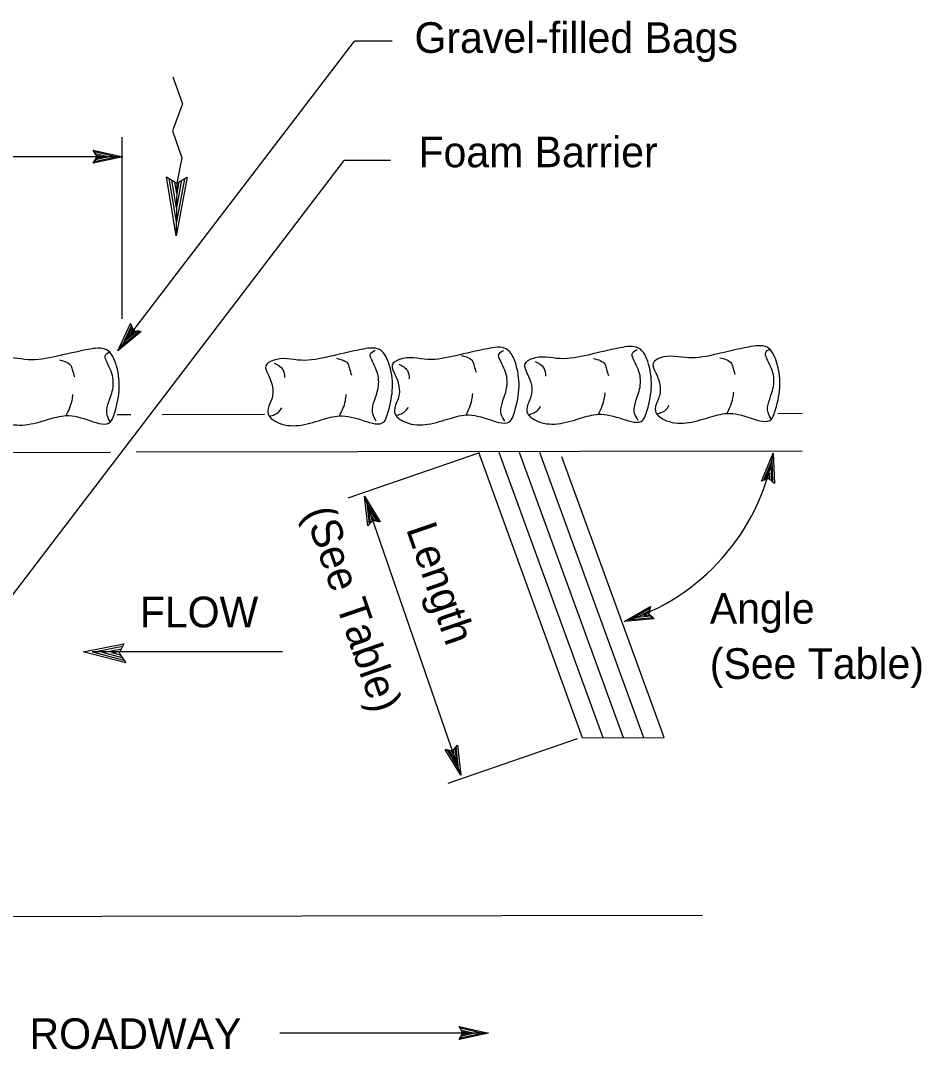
# Model space of a CAD drawing. Extents: x 6708945 to 6710368, y 1871409 to 1872338.
# Drawn here: x 6709914.8 to 6710091.1, y 1871506.8 to 1871708.2 of the extents above; entities that cross this region are included whole.
import ezdxf

# ---------------------------------------------------------------- set-up
doc = ezdxf.new("R2010")
doc.units = 0
for name, color, linetype in [('57 Undefined', 7, 'Continuous'), ('60 Nongeo Data', 7, 'Continuous'), ('63 Undefined', 7, 'Continuous')]:
    doc.layers.add(name, color=color, linetype=linetype)

msp = doc.modelspace()

# ---------------------------------------------------------------- linework, layer by layer
at = {"layer": '57 Undefined'}
for p, q in [((6709933.85, 1871643.55), (6709980.14, 1871704.21)), ((6709987.5, 1871704.21), (6709980.14, 1871704.21)), ((6709934.7, 1871649.82), (6709934.7, 1871685.42)), ((6709934.78, 1871681.58), (6709884.17, 1871681.58)), ((6709905.48, 1871585.64), (6709978.12, 1871680.81)), ((6709987.19, 1871680.81), (6709978.12, 1871680.81)), ((6710004.42, 1871623.57), (6709978.85, 1871614.76)), ((6710000.95, 1871560.49), (6709982.12, 1871615.15)), ((6710023.7, 1871567.6), (6709998.43, 1871558.89)), ((6710006.36, 1871510.02), (6709965.53, 1871510.02))]:
    msp.add_line(p, q, dxfattribs=at)
msp.add_arc((6710020.27, 1871631.22), 42.56, 287.3352, 349.5749, dxfattribs=at)
at = {"layer": '60 Nongeo Data'}
for p, q in [((6709929.02, 1871682.87), (6709929.02, 1871682.87)), ((6709934.78, 1871681.58), (6709934.78, 1871681.58)), ((6709929.02, 1871680.3), (6709929.02, 1871680.3)), ((6709936.33, 1871648.91), (6709936.33, 1871648.91)), ((6709938.36, 1871647.35), (6709938.36, 1871647.35)), ((6709933.85, 1871643.55), (6709933.85, 1871643.55)), ((6710024.8, 1871567.85), (6710004.48, 1871623.68)), ((6710028.79, 1871567.83), (6710008.46, 1871623.69)), ((6710032.77, 1871567.83), (6710012.44, 1871623.69)), ((6710036.76, 1871567.83), (6710016.42, 1871623.7)), ((6710040.73, 1871567.87), (6710020.73, 1871622.81)), ((6710062.12, 1871623.52), (6710062.12, 1871623.52)), ((6710059.82, 1871618.09), (6710059.82, 1871618.09)), ((6710062.34, 1871617.63), (6710062.34, 1871617.63)), ((6709982.12, 1871615.15), (6709982.12, 1871615.15)), ((6709982.78, 1871609.29), (6709982.78, 1871609.29)), ((6709985.2, 1871610.12), (6709985.2, 1871610.12)), ((6710038.07, 1871593.53), (6710038.07, 1871593.53)), ((6710032.95, 1871590.6), (6710032.95, 1871590.6)), ((6710038.83, 1871591.09), (6710038.83, 1871591.09)), ((6709927.04, 1871584.63), (6709934.97, 1871586.24)), ((6709935.39, 1871582.48), (6709927.04, 1871584.63)), ((6709927.04, 1871584.63), (6709927.04, 1871584.63)), ((6709966.02, 1871584.63), (6709928.77, 1871584.63)), ((6709935.04, 1871582.99), (6709928.91, 1871584.57)), ((6709928.92, 1871584.58), (6709934.71, 1871585.75)), ((6709930.79, 1871584.51), (6709934.52, 1871585.27)), ((6709934.66, 1871583.51), (6709930.79, 1871584.51)), ((6709932.66, 1871584.44), (6709934.26, 1871584.77)), ((6709934.37, 1871584), (6709932.66, 1871584.44)), ((6709934.97, 1871586.24), (6709934.09, 1871584.4)), ((6709934.09, 1871584.4), (6709935.39, 1871582.48)), ((6709934.97, 1871586.24), (6709934.97, 1871586.24)), ((6709935.39, 1871582.48), (6709935.39, 1871582.48)), ((6710000.29, 1871566.36), (6710000.29, 1871566.36)), ((6709997.87, 1871565.52), (6709997.87, 1871565.52)), ((6710000.95, 1871560.49), (6710000.95, 1871560.49)), ((6710000.6, 1871511.3), (6710000.6, 1871511.3)), ((6710006.36, 1871510.02), (6710006.36, 1871510.02)), ((6710000.6, 1871508.74), (6710000.6, 1871508.74))]:
    msp.add_line(p, q, dxfattribs=at)
for points in [[(6709929.02, 1871682.87), (6709934.78, 1871681.58), (6709929.02, 1871680.3), (6709929.22, 1871680.64), (6709933.44, 1871681.58), (6709929.22, 1871682.53), (6709929.43, 1871682.19), (6709932.13, 1871681.58), (6709929.43, 1871680.99), (6709929.63, 1871681.33), (6709930.8, 1871681.58), (6709929.63, 1871681.85), (6709929.79, 1871681.58), (6709929.02, 1871680.3), (6709929.79, 1871681.58)], [(6709938.36, 1871647.35), (6709933.85, 1871643.55), (6709936.33, 1871648.91), (6709936.47, 1871648.54), (6709934.65, 1871644.62), (6709937.97, 1871647.4), (6709937.58, 1871647.44), (6709935.46, 1871645.66), (6709936.62, 1871648.17), (6709936.77, 1871647.8), (6709936.26, 1871646.71), (6709937.18, 1871647.49), (6709936.88, 1871647.52), (6709936.33, 1871648.91), (6709936.88, 1871647.52)], [(6710059.82, 1871618.09), (6710062.12, 1871623.52), (6710062.34, 1871617.63), (6710062.04, 1871617.89), (6710061.89, 1871622.21), (6710060.19, 1871618.23), (6710060.56, 1871618.37), (6710061.64, 1871620.91), (6710061.74, 1871618.15), (6710061.45, 1871618.42), (6710061.4, 1871619.61), (6710060.93, 1871618.51), (6710061.22, 1871618.61), (6710062.34, 1871617.63), (6710061.22, 1871618.61)], [(6709982.78, 1871609.29), (6709982.12, 1871615.15), (6709985.2, 1871610.12), (6709984.81, 1871610.2), (6709982.56, 1871613.89), (6709983.04, 1871609.59), (6709983.29, 1871609.89), (6709982.98, 1871612.64), (6709984.43, 1871610.29), (6709984.04, 1871610.37), (6709983.41, 1871611.39), (6709983.55, 1871610.2), (6709983.75, 1871610.43), (6709985.2, 1871610.12), (6709983.75, 1871610.43)], [(6710038.83, 1871591.09), (6710032.95, 1871590.6), (6710038.07, 1871593.54), (6710037.97, 1871593.15), (6710034.22, 1871591), (6710038.54, 1871591.35), (6710038.24, 1871591.62), (6710035.48, 1871591.39), (6710037.88, 1871592.76), (6710037.79, 1871592.38), (6710036.75, 1871591.78), (6710037.95, 1871591.88), (6710037.72, 1871592.09), (6710038.07, 1871593.54), (6710037.72, 1871592.09)], [(6710000.29, 1871566.36), (6710000.95, 1871560.49), (6709997.87, 1871565.52), (6709998.26, 1871565.44), (6710000.52, 1871561.75), (6710000.04, 1871566.05), (6709999.78, 1871565.75), (6710000.09, 1871563), (6709998.65, 1871565.36), (6709999.04, 1871565.27), (6709999.66, 1871564.25), (6709999.53, 1871565.45), (6709999.33, 1871565.21), (6709997.87, 1871565.52), (6709999.33, 1871565.21)], [(6710000.6, 1871511.3), (6710006.36, 1871510.02), (6710000.6, 1871508.74), (6710000.8, 1871509.08), (6710005.02, 1871510.01), (6710000.8, 1871510.96), (6710001.01, 1871510.62), (6710003.71, 1871510.02), (6710001.01, 1871509.42), (6710001.21, 1871509.76), (6710002.38, 1871510.02), (6710001.21, 1871510.28), (6710001.37, 1871510.02), (6710000.6, 1871508.74), (6710001.37, 1871510.02)]]:
    msp.add_lwpolyline(points, close=True, dxfattribs=at)
for points in [[(6709933.67, 1871631.13), (6709936.36, 1871631.13)], [(6709942.48, 1871631.14), (6709962.52, 1871631.17)], [(6710063.01, 1871631.34), (6710067.78, 1871631.35)], [(6709678.2, 1871623.36), (6709932.4, 1871623.77)], [(6709937.44, 1871623.78), (6710067.78, 1871624)], [(6710024.8, 1871567.85), (6710040.73, 1871567.87)], [(6709578.14, 1871532.3), (6710048.25, 1871533.08)]]:
    msp.add_lwpolyline(points, dxfattribs=at)
for points in [[(6710039.45, 1871633.81), (6710039.05, 1871631.76), (6710040.71, 1871630.15), (6710049.45, 1871630.53), (6710053.03, 1871631.33), (6710057.81, 1871630.38), (6710061.76, 1871630.19), (6710062.38, 1871631.48), (6710062.84, 1871641.15), (6710060.89, 1871644.28), (6710057.25, 1871644.32), (6710051, 1871642.93), (6710045.53, 1871642.21), (6710039.98, 1871642.18), (6710038.6, 1871641.13), (6710039.12, 1871639.3), (6710039.84, 1871634.8), (6710039.37, 1871633.58)], [(6709910.11, 1871633.5), (6709909.69, 1871631.45), (6709911.34, 1871629.82), (6709920.08, 1871630.12), (6709923.67, 1871630.89), (6709928.44, 1871629.89), (6709932.39, 1871629.67), (6709933.02, 1871630.95), (6709933.57, 1871640.61), (6709931.65, 1871643.77), (6709928, 1871643.84), (6709921.75, 1871642.5), (6709916.26, 1871641.84), (6709910.72, 1871641.86), (6709909.33, 1871640.82), (6709909.83, 1871638.98), (6709910.51, 1871634.48), (6709910.03, 1871633.27)], [(6709932.38, 1871629.59), (6709931.73, 1871630.98), (6709932.64, 1871635.3), (6709932.85, 1871638.34), (6709931.54, 1871641.72), (6709931.33, 1871642.63), (6709932.33, 1871643.45)], [(6709963.61, 1871633.33), (6709963.22, 1871631.28), (6709964.87, 1871629.67), (6709973.62, 1871630.05), (6709977.19, 1871630.85), (6709981.97, 1871629.9), (6709985.92, 1871629.71), (6709986.54, 1871631), (6709987.01, 1871640.67), (6709985.06, 1871643.81), (6709981.41, 1871643.84), (6709975.17, 1871642.45), (6709969.69, 1871641.73), (6709964.14, 1871641.7), (6709962.77, 1871640.65), (6709963.28, 1871638.82), (6709964, 1871634.32), (6709963.54, 1871633.1)], [(6709984.4, 1871629.84), (6709983.73, 1871631.22), (6709984.6, 1871635.55), (6709984.78, 1871638.59), (6709983.44, 1871641.95), (6709983.22, 1871642.87), (6709984.22, 1871643.7)], [(6709988.38, 1871633.5), (6709987.99, 1871631.45), (6709989.64, 1871629.83), (6709998.39, 1871630.21), (6710001.96, 1871631.02), (6710006.74, 1871630.06), (6710010.69, 1871629.88), (6710011.31, 1871631.17), (6710011.78, 1871640.83), (6710009.83, 1871643.97), (6710006.18, 1871644), (6709999.94, 1871642.61), (6709994.46, 1871641.9), (6709988.91, 1871641.87), (6709987.54, 1871640.81), (6709988.05, 1871638.98), (6709988.77, 1871634.48), (6709988.31, 1871633.27)], [(6710009.55, 1871629.81), (6710008.88, 1871631.19), (6710009.75, 1871635.52), (6710009.93, 1871638.56), (6710008.59, 1871641.92), (6710008.37, 1871642.84), (6710009.37, 1871643.67)], [(6710014.3, 1871633.65), (6710013.9, 1871631.6), (6710015.56, 1871629.99), (6710024.3, 1871630.37), (6710027.88, 1871631.17), (6710032.66, 1871630.22), (6710036.61, 1871630.03), (6710037.23, 1871631.32), (6710037.69, 1871640.99), (6710035.74, 1871644.12), (6710032.09, 1871644.16), (6710025.85, 1871642.76), (6710020.37, 1871642.05), (6710014.83, 1871642.02), (6710013.45, 1871640.97), (6710013.97, 1871639.14), (6710014.69, 1871634.64), (6710014.22, 1871633.42)], [(6710035.65, 1871629.96), (6710034.98, 1871631.34), (6710035.86, 1871635.67), (6710036.03, 1871638.72), (6710034.7, 1871642.08), (6710034.48, 1871642.99), (6710035.47, 1871643.82)], [(6710061.76, 1871630.12), (6710061.09, 1871631.49), (6710061.96, 1871635.82), (6710062.14, 1871638.87), (6710060.8, 1871642.23), (6710060.58, 1871643.15), (6710061.57, 1871643.98)], [(6709922.42, 1871641.8), (6709924.68, 1871640.62), (6709924.97, 1871639.7), (6709925.33, 1871638.48)], [(6709964.45, 1871641.17), (6709966.11, 1871639.94), (6709966.47, 1871638.33)], [(6709976.61, 1871642.13), (6709978.88, 1871640.97), (6709979.18, 1871640.05), (6709979.55, 1871638.83)], [(6709988.83, 1871640.96), (6709990.49, 1871639.72), (6709990.86, 1871638.12)], [(6710001.01, 1871642.68), (6710003.28, 1871641.52), (6710003.57, 1871640.6), (6710003.94, 1871639.38)], [(6710015.51, 1871641.48), (6710017.17, 1871640.25), (6710017.54, 1871638.65)], [(6710026.91, 1871642.07), (6710029.18, 1871640.91), (6710029.48, 1871639.99), (6710029.85, 1871638.77)], [(6710051.68, 1871642.23), (6710053.95, 1871641.07), (6710054.25, 1871640.16), (6710054.62, 1871638.93)], [(6709923.67, 1871630.82), (6709924.86, 1871633.84), (6709925.04, 1871635.06)], [(6709977.19, 1871630.78), (6709978.36, 1871633.81), (6709978.52, 1871635.03)], [(6710001.96, 1871630.94), (6710003.13, 1871633.98), (6710003.29, 1871635.2)], [(6710027.88, 1871631.1), (6710029.04, 1871634.13), (6710029.21, 1871635.35)], [(6710053.03, 1871631.26), (6710054.2, 1871634.29), (6710054.36, 1871635.51)], [(6710014.12, 1871631.06), (6710016.11, 1871632.04), (6710016.57, 1871632.72)], [(6710039.28, 1871631.23), (6710041.26, 1871632.2), (6710041.72, 1871632.88)], [(6709963.44, 1871630.75), (6709965.42, 1871631.72), (6709965.89, 1871632.4)], [(6709988.21, 1871630.91), (6709990.19, 1871631.88), (6709990.66, 1871632.56)]]:
    msp.add_spline(points, degree=3, dxfattribs=at)
at = {"layer": '63 Undefined'}
for p, q in [((6709945.26, 1871666.07), (6709943.33, 1871677.63)), ((6709943.33, 1871677.63), (6709945.36, 1871676.43)), ((6709945.29, 1871668.83), (6709943.87, 1871677.31)), ((6709945.31, 1871671.57), (6709944.41, 1871676.99)), ((6709947.4, 1871677.59), (6709945.26, 1871666.07)), ((6709946.86, 1871677.28), (6709945.29, 1871668.83)), ((6709945.36, 1871676.43), (6709947.4, 1871677.59)), ((6709945.34, 1871674.37), (6709944.96, 1871676.67)), ((6709946.31, 1871676.97), (6709945.31, 1871671.57)), ((6709945.76, 1871676.66), (6709945.34, 1871674.37))]:
    msp.add_line(p, q, dxfattribs=at)
msp.add_lwpolyline([(6709944.59, 1871697.21), (6709946.45, 1871691.91), (6709944.5, 1871686.64), (6709946.35, 1871681.34), (6709945.36, 1871676.43), (6709945.26, 1871666.07)], dxfattribs=at)

# ---------------------------------------------------------------- texts
at = {"layer": '57 Undefined'}
for s, p in [('Gravel-filled Bags', (6709991.89, 1871701.91)), ('Foam Barrier', (6709992.67, 1871679.52)), ('Angle ', (6710049.69, 1871590.16)), ('(See Table)', (6710049.69, 1871579.36)), ('ROADWAY', (6709916.54, 1871506.91))]:
    msp.add_text(s, height=6, dxfattribs=at).set_placement(p)
for s, p in [('(See Table)', (6709970.25, 1871611.99)), ('Length', (6709990.19, 1871608.73))]:
    msp.add_text(s, height=6, rotation=289.0018, dxfattribs=at).set_placement(p)
at = {"layer": '60 Nongeo Data'}
msp.add_text('FLOW', height=6, dxfattribs=at).set_placement((6709938.13, 1871589.45))

doc.saveas('drawing.dxf')
